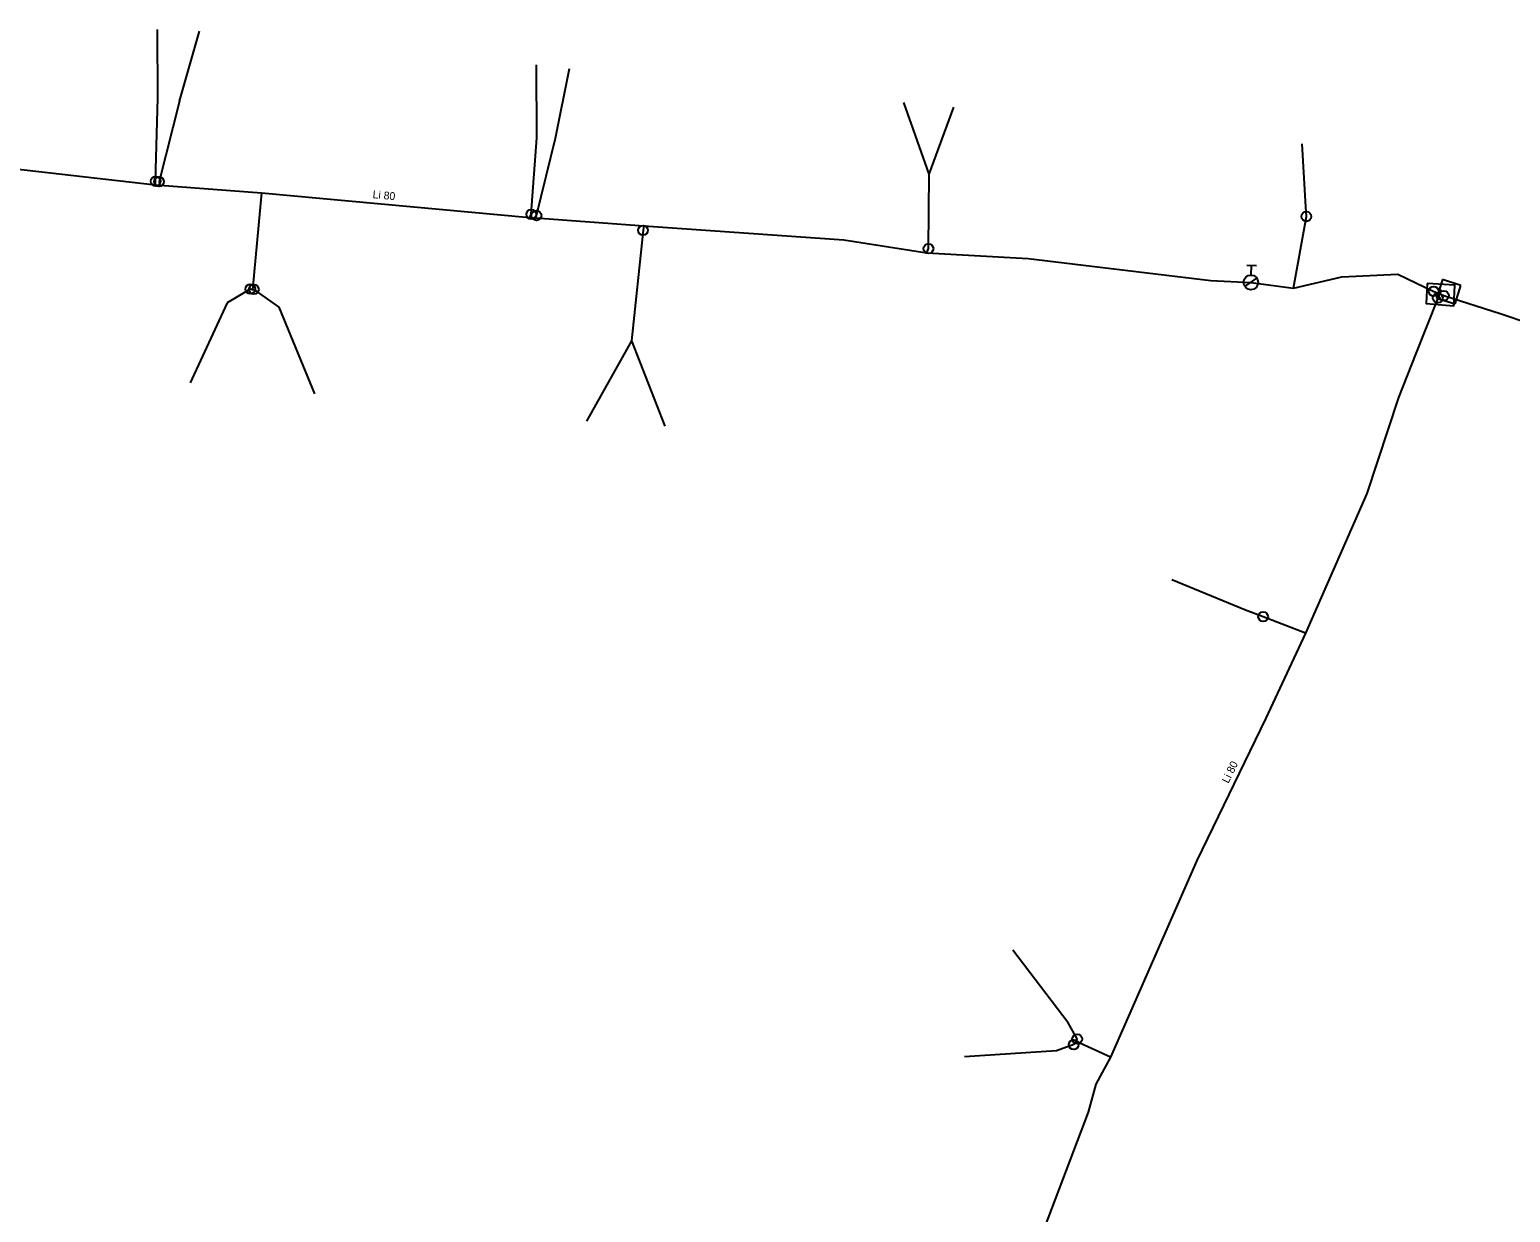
# Model space of a CAD drawing. Extents: x -684835 to -684548, y -1163297 to -1162881.
# Drawn here: x -684756.8 to -684680.9, y -1163087.1 to -1163026.4 of the extents above; entities that cross this region are included whole.
import ezdxf

# ---------------------------------------------------------------- set-up
doc = ezdxf.new("R2010")
doc.units = 0
for name, color, linetype in [('Hydranty', 7, 'Continuous'), ('Objekty podzemní', 7, 'Continuous'), ('Popis vodovodních řadů', 7, 'Continuous'), ('Vod přípojky-voda pitná', 7, 'Continuous'), ('Vodovodní řad', 7, 'Continuous'), ('Vodovodní šachty', 7, 'Continuous'), ('Vodovodní šoupata', 7, 'Continuous')]:
    doc.layers.add(name, color=color, linetype=linetype)

msp = doc.modelspace()

# ---------------------------------------------------------------- linework, layer by layer
at = {"layer": 'Hydranty'}
for p, q in [((-684694.401, -1163038.495), (-684693.902, -1163038.517)), ((-684694.174, -1163039.005), (-684694.152, -1163038.506)), ((-684694.494, -1163039.598), (-684693.884, -1163039.161))]:
    msp.add_line(p, q, dxfattribs=at)
msp.add_circle((-684694.19, -1163039.38), 0.375, dxfattribs=at)
at = {"layer": 'Objekty podzemní'}
msp.add_lwpolyline([(-684685.15, -1163039.43), (-684685.19, -1163040.47), (-684683.78, -1163040.58), (-684683.73, -1163039.52), (-684685.15, -1163039.43)], dxfattribs=at)
at = {"layer": 'Vod přípojky-voda pitná'}
for points in [[(-684750.27, -1163029.93), (-684750.29, -1163026.42)], [(-684749.15, -1163030.08), (-684748.12, -1163026.5)], [(-684730.82, -1163031.96), (-684730.84, -1163028.23)], [(-684729.87, -1163031.99), (-684729.14, -1163028.41)], [(-684750.39, -1163034.37), (-684750.38, -1163034.19), (-684750.27, -1163029.93)], [(-684749.15, -1163030.08), (-684750.2, -1163034.21), (-684750.17, -1163034.39)], [(-684710.7, -1163033.83), (-684711.99, -1163030.15)], [(-684710.7, -1163033.83), (-684709.43, -1163030.4)], [(-684731.18, -1163036.05), (-684731.11, -1163035.89), (-684730.82, -1163031.96)], [(-684730.89, -1163036.07), (-684730.84, -1163035.95), (-684729.87, -1163031.99)], [(-684691.37, -1163035.51), (-684691.56, -1163032.27)], [(-684710.73, -1163037.65), (-684710.7, -1163033.83)], [(-684744.94, -1163034.79), (-684745.4, -1163039.76)], [(-684692.01, -1163039.68), (-684691.34, -1163036), (-684691.37, -1163035.51)], [(-684725.34, -1163036.48), (-684725.37, -1163036.71), (-684725.97, -1163042.38)], [(-684710.82, -1163037.86), (-684710.73, -1163037.65)], [(-684745.4, -1163039.76), (-684745.52, -1163039.72), (-684746.7, -1163040.42)], [(-684745.4, -1163039.76), (-684745.34, -1163039.74), (-684744.05, -1163040.65)], [(-684746.7, -1163040.42), (-684748.61, -1163044.53)], [(-684744.05, -1163040.65), (-684742.22, -1163045.1)], [(-684725.97, -1163042.38), (-684728.28, -1163046.49)], [(-684725.97, -1163042.38), (-684724.25, -1163046.75)], [(-684694.47, -1163056.19), (-684698.25, -1163054.63)], [(-684691.38, -1163057.36), (-684693.56, -1163056.52), (-684694.47, -1163056.19)], [(-684703.57, -1163077.34), (-684706.4, -1163073.62)], [(-684703.16, -1163078.3), (-684703.1, -1163078.17), (-684703.57, -1163077.34)], [(-684701.39, -1163079.1), (-684703.16, -1163078.3), (-684703.28, -1163078.46), (-684704.16, -1163078.78)], [(-684704.14, -1163078.79), (-684704.16, -1163078.78), (-684708.88, -1163079.08)]]:
    msp.add_lwpolyline(points, dxfattribs=at)
at = {"layer": 'Vodovodní řad'}
for points in [[(-684791.912, -1163029.784), (-684791.66, -1163029.81), (-684779.55, -1163031.07), (-684768.26, -1163032.46), (-684764.58, -1163032.78), (-684764.32, -1163032.79), (-684750.39, -1163034.37), (-684750.17, -1163034.39), (-684744.94, -1163034.79), (-684731.18, -1163036.05), (-684730.89, -1163036.07), (-684725.34, -1163036.48), (-684715.08, -1163037.2), (-684710.82, -1163037.86), (-684705.62, -1163038.16), (-684696.25, -1163039.28), (-684694.19, -1163039.38), (-684692.01, -1163039.68), (-684689.52, -1163039.09), (-684686.65, -1163038.96)], [(-684686.65, -1163038.96), (-684684.81, -1163039.84)], [(-684684.45, -1163039.74), (-684684.53, -1163039.95)], [(-684684.6, -1163040.18), (-684685.72, -1163043.02), (-684686.62, -1163045.29), (-684688.25, -1163050.21), (-684691.38, -1163057.36), (-684693.43, -1163061.72), (-684696.97, -1163069.02), (-684701.39, -1163079.1), (-684702.15, -1163080.49), (-684702.53, -1163081.93), (-684704.79, -1163087.87), (-684705.98, -1163090.06)], [(-684684.81, -1163039.84), (-684684.53, -1163039.95)], [(-684684.53, -1163039.95), (-684684.6, -1163040.18)], [(-684684.53, -1163039.95), (-684684.29, -1163040.06)], [(-684684.29, -1163040.06), (-684681.41, -1163040.97), (-684676.84, -1163042.51), (-684668.9, -1163044.76), (-684663.71, -1163046.07), (-684661.75, -1163046.57), (-684661.09, -1163046.82), (-684636.19, -1163053.94), (-684630.3, -1163055.66), (-684608.07, -1163062.56), (-684588.21, -1163068.29), (-684579.289, -1163070.99)]]:
    msp.add_lwpolyline(points, dxfattribs=at)
at = {"layer": 'Vodovodní šachty'}
for p, q in [((-684684.366, -1163039.233), (-684684.667, -1163040.186)), ((-684683.413, -1163039.534), (-684684.366, -1163039.233)), ((-684683.714, -1163040.487), (-684683.413, -1163039.534)), ((-684684.667, -1163040.186), (-684683.714, -1163040.487))]:
    msp.add_line(p, q, dxfattribs=at)
at = {"layer": 'Vodovodní šoupata'}
for centre in [(-684750.38, -1163034.19), (-684750.2, -1163034.21), (-684731.11, -1163035.89), (-684730.84, -1163035.95), (-684691.34, -1163036), (-684725.37, -1163036.71), (-684710.73, -1163037.65), (-684745.52, -1163039.72), (-684745.34, -1163039.74), (-684684.81, -1163039.84), (-684684.6, -1163040.18), (-684684.29, -1163040.06), (-684693.56, -1163056.52), (-684703.28, -1163078.46), (-684703.1, -1163078.17)]:
    msp.add_circle(centre, 0.25, dxfattribs=at)

# ---------------------------------------------------------------- texts
at = {"layer": 'Popis vodovodních řadů'}
for rotation, p in [(354.76803, (-684739.258, -1163035.059)), (64.12979, (-684695.344, -1163065.093))]:
    msp.add_text('Li 80', height=0.4, rotation=rotation, dxfattribs=at).set_placement(p)

doc.saveas('drawing.dxf')
